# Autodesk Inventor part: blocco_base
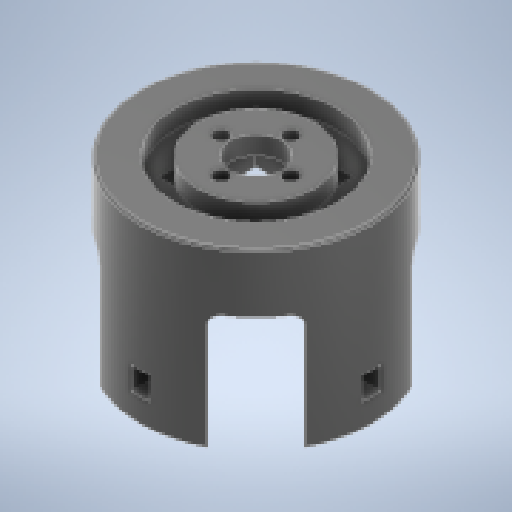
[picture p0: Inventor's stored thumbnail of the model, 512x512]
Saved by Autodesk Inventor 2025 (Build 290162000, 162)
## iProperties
Created: 2026-03
Part Number: blocco_base
Material: Plastica ABS
Document SubType Name: Modeling
Designer: R5800u
Density: 1.06 g/cm^3
Appearance: Liscia - Nero
Author: R5800u
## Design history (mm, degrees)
sketch "Schizzo1"
  geometry: L1 (21, -21)-(-21, -21); L2 (-21, -21)-(-21, 21); L3 (-21, 21)-(21, 21); L4 (21, 21)-(21, -21); L5 (21, -21)-(-21, 21); L6 (-21, -21)-(21, 21); C1 r 50 at (0, 0); 1 further point
  constraints: 12 end point, 2 midpoint, 2 parallel, 1 centre point, 1 coincident, 1 horizontal, 1 perpendicular
  dimensions: "d0" = 100 diameter of C1; "d1" = 42 distance of L2.end L3.end; "d2" = 42 distance of L1.end L2.end
extrude "Estrusione1" new body sketch "Schizzo1" distance "d3" = 67.2; taper "d4" = 0 deg
sketch "Schizzo2"
  geometry: L1 (-21, 21)-(21, 21) reference; L2 (21, 21)-(21, -21) reference; L3 (21, -21)-(-21, -21) reference; L4 (-21, -21)-(-21, 21) reference; C1 r 35 at (0, 0); C2 r 50 at (0, 0) reference; C3 r 50 at (0, 0) reference; C4 r 25 at (0, 0); C5 r 11.1 at (0, 0); 1 further point
  constraints: 3 centre point, 3 coincident
  dimensions: "d5" = 70 diameter of C1; "d8" = 50 diameter of C4; "d9" = 22.2 diameter of C5
extrude "Estrusione2" join sketch "Schizzo2" distance "d6" = 8; taper "d7" = 0 deg
sketch "Schizzo3"
  geometry: C1 r 1.621 at (0, -15) reference; C2 r 1.621 at (-15, 0) reference; C3 r 1.621 at (15, 0) reference; C4 r 1.621 at (0, 15) reference; 1 further point
hole "Foro1" sketch "Schizzo3" at (-15, 0), (0, -15), (15, 0), (0, 15) diameter "d10" = 4.5; stored, may be unused: countersink angle "d14" = 82 deg, drill point angle "d16" = 118 deg; dims "d11" = 8, "d12" = 6.5, "d13" = 4.6, "d15" = 11.8
node "Piano di lavoro1"
sketch "Schizzo4"
  geometry: L1 (45.464, 2)-(46.619, 0) reference; L2 (44.309, 4)-(45.464, 2) reference; L3 (42, 4)-(44.309, 4) reference; L4 (46.619, 0)-(45.464, -2) reference; L5 (45.464, -2)-(44.309, -4) reference; L6 (44.309, -4)-(42, -4) reference; L7 (42, -4)-(39.691, -4) reference; L8 (39.691, -4)-(38.536, -2) reference; L9 (38.536, -2)-(37.381, 0) reference; L10 (37.381, 0)-(38.536, 2) reference; L11 (38.536, 2)-(39.691, 4) reference; L12 (39.691, 4)-(42, 4) reference; L13 (44.309, 4)-(49.84, 4); L14 (44.309, -4)-(49.84, -4); A1 r 50 centre (0, 0) between (49.84, 4) and (49.84, -4) reference; A2 r 50 centre (0, 0) between (49.84, 4) and (49.84, -4) reference
  constraints: 4 end point, 2 point on circle, 1 horizontal, 1 parallel
extrude "Estrusione3" cut sketch "Schizzo4" distance "d18" = 10; taper "d19" = 0 deg
sketch "Schizzo5"
  geometry: C1 r 2.65 at (65, 0) reference; 1 further point
extrude "Estrusione4" cut sketch "Schizzo5" distance "d20" = 25; taper "d21" = 0 deg
pattern_circular "Serie circolare1" dims "d23" = 360 deg
node "Piano di lavoro2"
sketch "Schizzo6"
  geometry: L1 (-50, -15)-(50, -15); L2 (50, -15)-(50, 15); L3 (50, 15)-(-50, 15); L4 (-50, 15)-(-50, -15); L5 (-50, -15)-(50, 15); L6 (50, -15)-(-50, 15); 1 further point
  constraints: 12 end point, 2 midpoint, 2 parallel, 1 horizontal, 1 perpendicular
  dimensions: "d26" = 100 distance of L3.end L2.end; "d27" = 30 distance of L2.end L1.end
extrude "Estrusione5" cut sketch "Schizzo6" extent not by distance; stored distance "d28" = 0; taper "d29" = 0 deg
pattern_circular "Serie circolare2" dims angle "d31" = 360 deg
fillet "Raccordo1" dims "d33" = 5
fillet "Raccordo2" dims "d34" = 1
sketch "Schizzo8"
  geometry: C1 r 2.65 at (42, 0) reference; 1 further point
hole "Foro3" sketch "Schizzo8" at (42, 0) diameter "d42" = 5.5; stored, may be unused: countersink angle "d46" = 90 deg, drill point angle "d48" = 118 deg; dims "d43" = 6, "d44" = 4, "d45" = 2, "d47" = 25
pattern_circular "Serie circolare3" dims angle "d50" = 360 deg
node "Solido1"
node "Linea chiusa proiettata1"
node "Riferimento1"
node "Riferimento2"
node "Riferimento3"
node "Riferimento4"
node "Riferimento12"
node "Riferimento13"
node "Riferimento14"
node "Riferimento15"
node "Riferimento16"
node "Riferimento17"
node "Riferimento18"
node "Riferimento19"
node "Riferimento20"
node "Riferimento21"
node "Riferimento22"
node "Riferimento23"
node "Riferimento24"
node "Riferimento26"
other parameters: "d25" = 45 deg
